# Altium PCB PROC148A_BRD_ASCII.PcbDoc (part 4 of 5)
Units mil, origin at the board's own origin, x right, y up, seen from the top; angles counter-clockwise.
Board outline 7150 x 3764 mil, 4 copper layers (Top Layer, GND01, PWR/GND02, Bottom Layer), stack 60.96 mil thick; 312 components, 352 nets, 2206 pads, 423 vias.
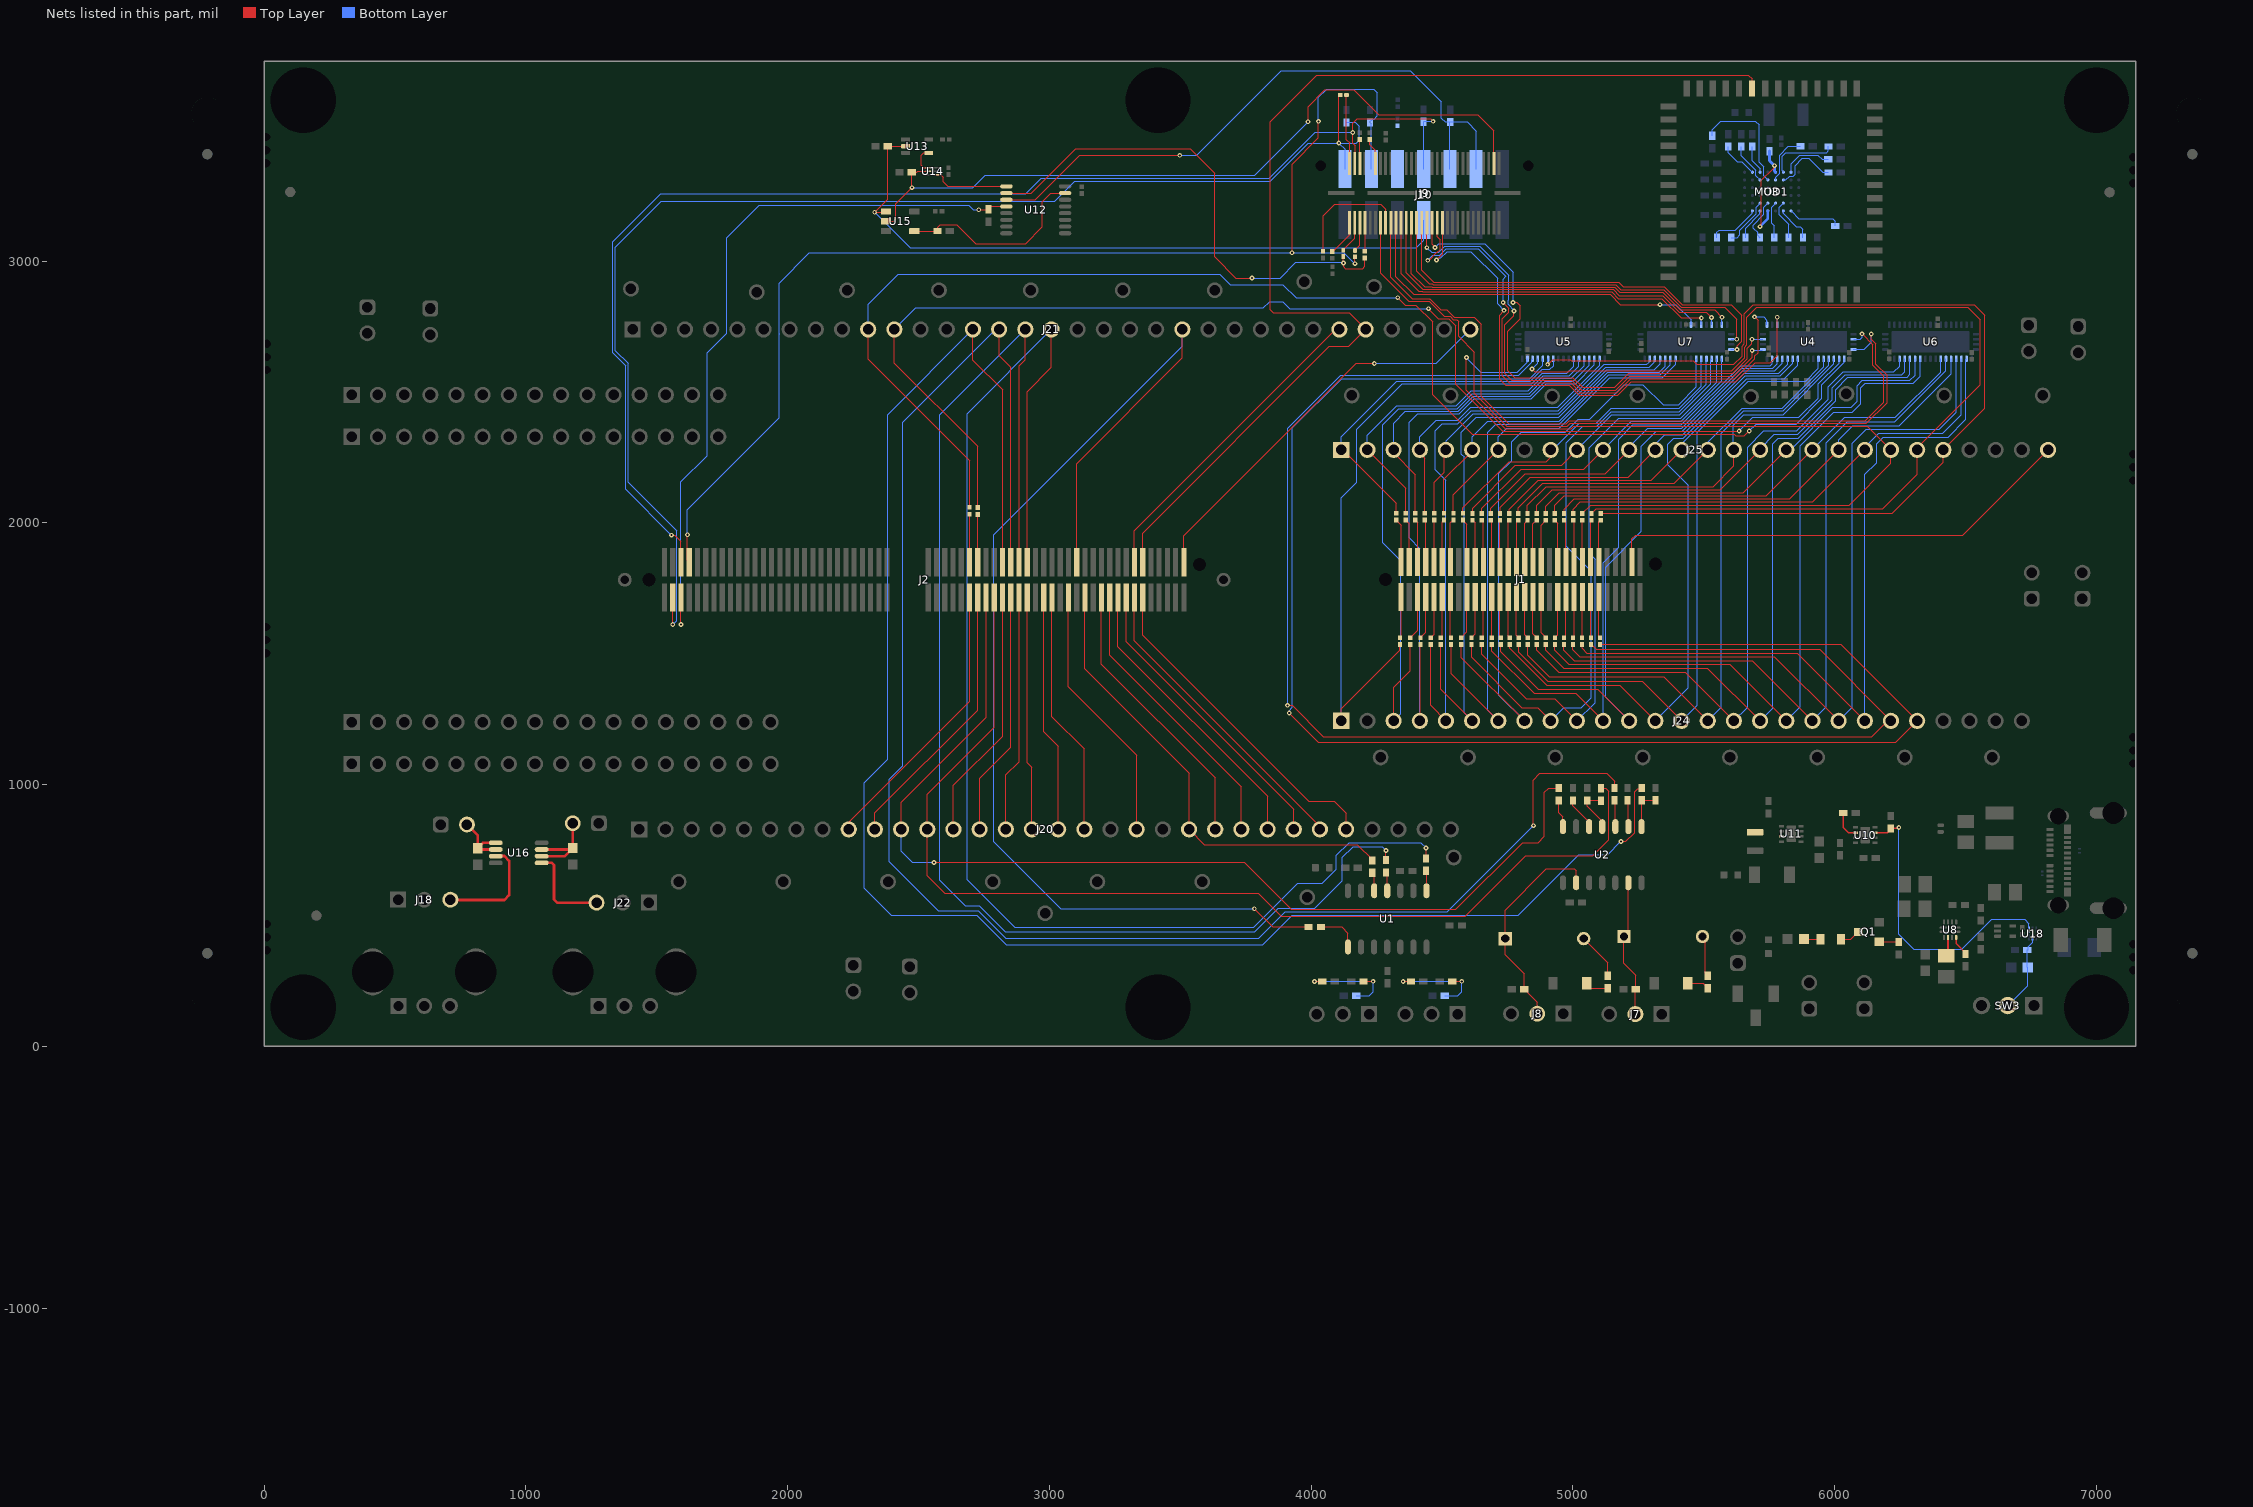
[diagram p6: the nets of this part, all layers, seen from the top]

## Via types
v1: diameter 18, hole 8, Top Layer to Bottom Layer, tented both sides, 422 vias
v2: diameter 18, hole 8, Top Layer to Bottom Layer, 1 vias

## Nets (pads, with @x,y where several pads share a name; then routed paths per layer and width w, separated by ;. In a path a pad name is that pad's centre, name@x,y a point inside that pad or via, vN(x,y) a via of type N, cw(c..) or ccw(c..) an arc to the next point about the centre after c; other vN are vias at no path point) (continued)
HSEC_GPMC0_A0: J25.2 R29.2 U5.6 | length 1303.9
  Top Layer w4: J25.2@4215,2279 4361.43,2132.57 R29.2@4361.43,2037
  Bottom Layer w4: J25.2@4215,2279 4215,2334.41 4327.3,2446.71 4553.99,2446.71 4611.52,2504.24 4829.01,2504.24 4886.53,2561.76 4986.25,2561.76 5023.17,2598.68 U5.6@5023.17,2626.92
HSEC_GPMC0_A1: J24.3 R30.1 U5.5 | length 2376.2
  Top Layer w4: J24.3@4315,1244 4315,1372.51 4378.37,1435.88 R30.1@4378.37,1535
  Bottom Layer w4: J24.3@4315,1244 4342,1271 4342,1855.56 4274.22,1923.34 4274.22,2375.64 4335.29,2436.71 4558.72,2436.71 4616.24,2494.24 4833.15,2494.24 4890.67,2551.76 4993.88,2551.76 5042.86,2600.74 U5.5@5042.86,2626.92
HSEC_GPMC0_A2: J25.3 R31.2 U5.4 | length 1242.1
  Top Layer w4: J25.3@4315,2279 4315,2267.16 4397.86,2184.3 R31.2@4397.86,2037
  Bottom Layer w4: J25.3@4315,2279 4315,2381.36 4360.35,2426.71 4562.36,2426.71 4619.88,2484.24 4837.29,2484.24 4894.81,2541.76 5001.51,2541.76 5062.54,2602.8 U5.4@5062.54,2626.92
HSEC_GPMC0_A3: J24.4 R32.1 U5.3 | length 2271.1
  Top Layer w4: J24.4@4415,1244 4415,1275 4417.4,1277.4 R32.1@4417.4,1535
  Bottom Layer w4: J24.4@4415,1244 4415,1901.65 4374.22,1942.43 4374.22,2383.52 4407.41,2416.71 4565.27,2416.71 4622.79,2474.24 4841.43,2474.24 4898.96,2531.76 5010.73,2531.76 5082.23,2603.25 U5.3@5082.23,2626.92
HSEC_GPMC0_A4: J25.4 R33.2 U5.2 | length 1125
  Top Layer w4: J25.4@4415,2279 4415,2266.4 4434.29,2247.11 R33.2@4434.29,2037
  Bottom Layer w4: J25.4@4415,2279 4415,2329 4477.28,2391.28 4559.36,2391.28 4609.36,2441.28 4941.36,2441.28 5101.91,2601.82 U5.2@5101.91,2626.92
HSEC_GPMC0_A5: J24.5 R34.1 U7.16 | length 2379.2
  Top Layer w4: R34.1@4456.43,1535 4456.43,1302.57 J24.5@4515,1244
  Bottom Layer w4: J24.5@4515,1244 4515,2162.73 4474.22,2203.51 4474.22,2352.01 4500.15,2377.94 4560.17,2377.94 4610.95,2428.73 4943.92,2428.73 5120.43,2605.24 5129.45,2605.24 5281.8,2605.24 5290.7,2614.14 5290.7,2624 U7.16@5293.62,2626.92
HSEC_GPMC0_A6: J25.5 R35.2 U7.15 | length 1228.4
  Top Layer w4: R35.2@4470.71,2037 4470.71,2155.99 4508.3,2193.58 4508.3,2272.3 J25.5@4515,2279
  Bottom Layer w4: J25.5@4515,2279 4516.34,2280.34 4516.34,2313.56 4619.12,2416.35 4945.68,2416.35 5124.57,2595.24 5292.08,2595.24 5310.39,2613.54 5310.39,2624 U7.15@5313.31,2626.92
HSEC_GPMC0_A7: J24.6 R40.1 U7.14 | length 2345.3
  Top Layer w4: R40.1@4495.46,1535 4495.46,1363.54 J24.6@4615,1244
  Bottom Layer w4: J24.6@4615,1244 4584.17,1274.83 4584.17,2252.16 4574.22,2262.11 4574.22,2345.89 4631.35,2403.02 4946.49,2403.02 5128.71,2585.24 5309.71,2585.24 5332.99,2608.51 U7.14@5332.99,2626.92
HSEC_GPMC0_A8: J25.6 R41.2 U7.13 | length 1214.4
  Top Layer w4: R41.2@4507.14,2037 4507.14,2166.01 4615,2273.87 J25.6@4615,2279
  Bottom Layer w4: J25.6@4615,2279 4615,2329 4675.21,2389.21 4946.83,2389.21 5132.86,2575.24 5329.34,2575.24 5352.68,2598.58 U7.13@5352.68,2626.92
HSEC_GPMC0_A9: J24.7 R42.1 U7.12 | length 2312.5
  Top Layer w4: R42.1@4534.48,1535 4534.48,1424.52 J24.7@4715,1244
  Bottom Layer w4: J24.7@4715,1244 4674.22,1284.78 4674.22,2345.89 4704.21,2375.88 4947.64,2375.88 5137,2565.24 5333.48,2565.24 5372.36,2604.12 U7.12@5372.36,2626.92
HSEC_GPMC0_A10: J25.7 R43.2 U7.11 | length 1175.5
  Top Layer w4: R43.2@4543.57,2037 4543.57,2107.57 J25.7@4715,2279
  Bottom Layer w4: J25.7@4715,2279 4715,2329 4747.59,2361.59 4947.5,2361.59 5141.14,2555.23 5340.96,2555.23 5392.05,2606.32 U7.11@5392.05,2626.92
HSEC_GPMC0_A11_TRC_DATA4: J24.10 R98.1 U7.3 | length 2267.9
  Top Layer w4: R98.1@4651.56,1535 4651.56,1498.44 4821.1,1328.9 4930.1,1328.9 J24.10@5015,1244
  Bottom Layer w4: J24.10@5015,1244 5084.4,1313.4 5084.4,1860.72 5061.68,1883.44 5061.68,2287.95 5174.37,2400.64 5412.35,2400.64 5549.53,2537.82 U7.3@5549.53,2626.92
HSEC_GPMC0_A12_TRC_DATA5: J25.11 R99.2 U7.2 | length 1222.6
  Top Layer w4: R99.2@4651.56,2035.98 4651.56,2055.2 4801.88,2205.52 5041.52,2205.52 J25.11@5115,2279
  Bottom Layer w4: J25.11@5115,2279 5223.67,2387.67 5413.52,2387.67 5569.21,2543.36 U7.2@5569.21,2626.92
HSEC_GPMC0_A13_TRC_DATA6: J24.11 R100.1 U4.16 | length 2385.9
  Top Layer w4: R100.1@4689.76,1535.51 4689.76,1510.24 4851.65,1348.35 5010.65,1348.35 J24.11@5115,1244
  Bottom Layer w4: J24.11@5115,1244 5115,1847.83 5174.22,1907.05 5174.22,2319.55 5229,2374.33 5414.32,2374.33 5641.21,2601.22 5753.96,2601.22 5760.92,2608.18 U4.16@5760.92,2626.92
HSEC_GPMC0_A14_TRC_DATA7: J25.12 R101.2 U4.15 | length 1368.5
  Top Layer w4: R101.2@4686.5,2035.98 4686.5,2055.95 4817.37,2186.82 5122.82,2186.82 J25.12@5215,2279
  Bottom Layer w4: J25.12@5215,2279 5215,2291.42 5285.17,2361.59 5415.73,2361.59 5645.36,2591.22 5763.13,2591.22 5780.61,2608.7 U4.15@5780.61,2626.92
HSEC_GPMC0_A15_TRC_DATA8: J24.12 R102.1 U4.14 | length 2457.3
  Top Layer w4: R102.1@4724.26,1535.51 4724.26,1508.13 4868.07,1364.32 5094.68,1364.32 J24.12@5215,1244
  Bottom Layer w4: J24.12@5215,1244 5125,1334 5125,1830.87 5261.7,1967.57 5261.7,2293.47 5318.09,2349.86 5418.14,2349.86 5649.5,2581.22 5771.07,2581.22 5800.29,2610.44 U4.14@5800.29,2626.92
HSEC_GPMC0_A16_TRC_DATA9: J25.13 R103.2 U4.13 | length 1382.5
  Top Layer w4: R103.2@4721.43,2035.98 4721.43,2059.39 4837.1,2175.05 5211.05,2175.05 J25.13@5315,2279
  Bottom Layer w4: J25.13@5315,2279 5315,2300.81 5351.01,2336.82 5419.24,2336.82 5653.64,2571.22 5786,2571.22 5819.98,2605.2 U4.13@5819.98,2626.92
HSEC_GPMC0_A17_TRC_DATA10: J24.13 R104.1 U4.12 | length 2450.1
  Top Layer w4: R104.1@4758.75,1535.51 4758.75,1520.25 4899.54,1379.46 5179.54,1379.46 J24.13@5315,1244
  Bottom Layer w4: J24.13@5315,1244 5440.96,1369.96 5440.96,2143.92 5361.89,2222.99 5361.89,2299.84 5385.13,2323.08 5420.7,2323.08 5658.84,2561.22 5791.31,2561.22 5839.66,2609.57 U4.12@5839.66,2626.92
HSEC_GPMC0_A18_TRC_DATA11: J25.14 R105.2 U4.11 | length 1385.2
  Top Layer w4: R105.2@4756.36,2035.98 4756.36,2051.36 4868.28,2163.28 5299.28,2163.28 J25.14@5415,2279
  Bottom Layer w4: J25.14@5415,2279 5415,2303.08 5663.14,2551.22 5808.15,2551.22 5859.35,2602.42 U4.11@5859.35,2626.92
HSEC_GPMC0_A19_TRC_DATA12: J24.14 R106.1 U4.7 | length 2488.1
  Top Layer w4: R106.1@4793.25,1535.51 4793.25,1505.38 4904.01,1394.61 5264.39,1394.61 J24.14@5415,1244
  Bottom Layer w4: J24.14@5415,1244 5474.22,1303.22 5474.22,2345.89 5669.55,2541.22 5888.68,2541.22 5938.09,2590.63 U4.7@5938.09,2626.92
HSEC_GPMC0_A20_TRC_DATA13: J25.15 R107.2 U4.6 | length 1458.5
  Top Layer w4: R107.2@4791.3,2035.98 4791.3,2057.61 4885.2,2151.51 5387.51,2151.51 J25.15@5515,2279
  Bottom Layer w4: J25.15@5515,2279 5515,2307.25 5646.09,2438.34 5799.94,2438.34 5957.77,2596.17 U4.6@5957.77,2626.92
HSEC_GPMC0_A21_TRC_DATA14: J24.15 R108.1 U4.5 | length 2495.3
  Top Layer w4: R108.1@4827.74,1535.51 4827.74,1494.5 4910.06,1412.18 5346.82,1412.18 J24.15@5515,1244
  Bottom Layer w4: J24.15@5515,1244 5566.4,1295.4 5566.4,2342.16 5652.58,2428.34 5804.09,2428.34 5977.46,2601.71 U4.5@5977.46,2626.92
HSEC_GPMC0_AD0: J24.16 R110.1 U6.15 | length 2719
  Top Layer w4: R110.1@4862.23,1535.51 4862.23,1512.82 4945.14,1429.91 5429.09,1429.91 J24.16@5615,1244
  Bottom Layer w4: J24.16@5615,1244 5667.16,1296.16 5667.16,2288.83 5729.5,2351.17 5855.59,2351.17 5976.13,2471.71 5976.13,2520.89 6032.71,2577.47 6226.07,2577.47 6247.91,2599.31 U6.15@6247.91,2626.92
HSEC_GPMC0_AD1: J25.17 R111.2 U6.14 | length 1728
  Top Layer w4: R111.2@4861.16,2035.98 4861.16,2066.45 4921.35,2126.63 5562.63,2126.63 J25.17@5715,2279
  Bottom Layer w4: J25.17@5715,2279 5715,2283.59 5769.37,2337.96 5857.93,2337.96 5989.75,2469.78 5989.75,2516.5 6039.92,2566.67 6256.67,2566.67 6267.6,2577.6 U6.14@6267.6,2626.92
HSEC_GPMC0_AD2: J24.17 R112.1 U6.13 | length 2748
  Top Layer w4: R112.1@4896.73,1535.51 4896.73,1513.74 4965.05,1445.42 5513.58,1445.42 J24.17@5715,1244
  Bottom Layer w4: J24.17@5715,1244 5763.6,1292.6 5763.6,2301.51 5785.16,2323.08 5860.1,2323.08 6003.12,2466.1 6003.12,2509.41 6050.38,2556.67 6276.27,2556.67 6287.28,2567.68 U6.13@6287.28,2626.92
HSEC_GPMC0_AD3: J25.18 R113.2 U6.12 | length 1743.9
  Top Layer w4: R113.2@4896.1,2035.98 4896.1,2063.85 4947.24,2115 5651,2115 J25.18@5815,2279
  Bottom Layer w4: J25.18@5815,2279 5825.9,2289.9 5840.87,2289.9 5992.34,2441.37 6063.41,2441.37 6086.43,2464.39 6086.43,2524.78 6105.67,2544.02 6286.52,2544.02 6306.77,2564.27 6306.77,2626.72 U6.12@6306.97,2626.92
HSEC_GPMC0_AD4: J24.18 R114.1 U6.11 | length 2761.3
  Top Layer w4: R114.1@4931.22,1535.51 4931.22,1513.74 4984.35,1460.61 5598.39,1460.61 J24.18@5815,1244
  Bottom Layer w4: J24.18@5815,1244 5868.63,1297.63 5868.63,2294.08 5997.02,2422.47 6067.15,2422.47 6099.3,2454.62 6099.3,2516.84 6116.48,2534.02 6300.97,2534.02 6326.65,2559.7 U6.11@6326.65,2626.92
HSEC_GPMC0_AD5: J25.19 R115.2 U6.7 | length 1766.8
  Top Layer w4: R115.2@4931.03,2035.98 4931.03,2066.81 4967.59,2103.37 5739.37,2103.37 J25.19@5915,2279
  Bottom Layer w4: J25.19@5915,2279 6038.79,2402.79 6231.79,2402.79 6405.39,2576.39 U6.7@6405.39,2626.92
HSEC_GPMC0_AD6: J24.19 R116.1 U6.6 | length 2782.7
  Top Layer w4: R116.1@4965.72,1535.51 4965.72,1514.06 5005.97,1473.81 5685.19,1473.81 J24.19@5915,1244
  Bottom Layer w4: J24.19@5915,1244 5967.82,1296.82 5967.82,2305.39 6048.3,2385.87 6229.01,2385.87 6425.08,2581.93 U6.6@6425.08,2626.92
HSEC_GPMC0_AD7: J25.20 R117.2 U6.5 | length 1789.7
  Top Layer w4: R117.2@4965.97,2035.98 4965.97,2053 5004.47,2091.5 5827.5,2091.5 J25.20@6015,2279
  Bottom Layer w4: J25.20@6015,2279 6015,2318.16 6068.47,2371.63 6246.26,2371.63 6444.76,2570.13 U6.5@6444.76,2626.92
HSEC_GPMC0_AD8: J24.20 R118.1 U6.4 | length 2880
  Top Layer w4: R118.1@5000.21,1535.51 5000.21,1514.88 5025.73,1489.36 5769.64,1489.36 J24.20@6015,1244
  Bottom Layer w4: J24.20@6015,1244 6066.47,1295.47 6066.47,2303.31 6121.39,2358.23 6400.21,2358.23 6464.45,2422.47 U6.4@6464.45,2626.92
HSEC_GPMC0_AD9: J25.21 R119.2 U6.3 | length 1868.7
  Top Layer w4: R119.2@5000.9,2035.98 5000.9,2052.48 5028.28,2079.86 5915.86,2079.86 J25.21@6115,2279
  Bottom Layer w4: J25.21@6115,2279 6115,2289.73 6167.43,2342.16 6412.3,2342.16 6484.13,2413.99 U6.3@6484.13,2626.92
HSEC_GPMC0_AD10: J24.21 R120.1 U6.2 | length 2900
  Top Layer w4: R120.1@5034.71,1535.51 5034.71,1520.21 5053,1501.92 5857.08,1501.92 J24.21@6115,1244
  Bottom Layer w4: J24.21@6115,1244 6115,2185.96 6159.72,2230.68 6159.72,2303.03 6184.71,2328.02 6434,2328.02 6501.08,2395.1 6501.08,2624.19 U6.2@6503.82,2626.92
HSEC_GPMC0_AD11: J25.22 R121.2 U5.16 | length 3443.8
  Top Layer w4: v1(4593.12,2631.41) 4593.12,2507.62 4741.48,2359.25 4992.76,2359.25 5003.55,2370.04 6123.96,2370.04 J25.22@6215,2279 6215,2227.25 6055.8,2068.05 5067.9,2068.05 R121.2@5035.83,2035.98
  Bottom Layer w4: v1(4593.12,2631.41) 4648.4,2576.13 4787.9,2576.13 4826.32,2614.55 U5.16@4826.32,2626.92
HSEC_GPMC0_AD12: J24.22 R122.1 U5.15 | length 5756.5
  Top Layer w4: v1(3909.84,1303.13) 3926.91,1303.13 4046.68,1183.36 6142.26,1183.36 6202.9,1244 J24.22@6215,1244 5942.64,1516.36 5088.35,1516.36 R122.1@5069.2,1535.51
  Bottom Layer w4: v1(3909.84,1303.13) 3909.84,2361.58 4112.89,2564.63 4793.16,2564.63 4843.09,2614.55 4843.09,2624 U5.15@4846.01,2626.92
HSEC_GPMC0_AD13: J25.23 R123.2 U5.14 | length 3970.1
  Top Layer w4: v1(4843.69,2588.04) 4854.97,2576.76 4981.71,2576.76 4986.49,2581.54 5605.84,2581.54 5655.87,2631.57 5655.87,2670.78 5664.83,2679.74 5664.83,2786.11 5702.19,2823.47 6103.75,2823.47 6104.98,2824.7 6507.44,2824.7 6556.51,2775.63 6556.51,2528.18 6315,2286.67 J25.23@6315,2279 6315,2186.35 6183.56,2054.91 5088.91,2054.91 5070.77,2036.77 R123.2@5070.77,2035.98
  Bottom Layer w4: v1(4843.69,2588.04) 4865.69,2610.04 U5.14@4865.69,2626.92
HSEC_GPMC0_AD14: J24.23 R124.1 U5.13 | length 5985.2
  Top Layer w4: v1(3916.41,1273.55) 4027.17,1162.79 6233.79,1162.79 J24.23@6315,1244 6023.49,1535.51 R124.1@5103.69,1535.51
  Bottom Layer w4: v1(3916.41,1273.55) 3916.41,1283.01 3928.71,1295.31 3928.71,2363.31 4116.63,2551.23 4834.16,2551.23 4884.71,2601.78 4884.71,2626.25 U5.13@4885.38,2626.92
HSEC_GPMC0_AD15: J25.24 R125.2 U5.12 | length 3924.5
  Top Layer w4: v1(4903.58,2605.63) 4905.19,2605.63 4922.88,2623.32 4990.53,2623.32 4994.26,2619.59 5459.95,2619.59 5473.06,2606.48 5615.15,2606.48 5645.87,2637.2 5645.87,2674.92 5654.83,2683.88 5654.83,2799.29 5688.01,2832.47 6100.02,2832.47 6101.25,2833.7 6532.59,2833.7 6573.5,2792.79 6573.5,2437.5 J25.24@6415,2279 6415,2230.84 6220.14,2035.98 R125.2@5105.7,2035.98
  Bottom Layer w4: v1(4903.58,2605.63) 4904.32,2606.37 4904.32,2626.18 U5.12@4905.06,2626.92
HSEC_GPMC0_BE0N_CLE_TRC_DATA1: J25.9 R45.2 U7.6 | length 1249.5
  Top Layer w4: R45.2@4580,2037 4580,2056.9 4757.02,2233.92 4897.47,2233.92 4922.35,2258.8 4922.35,2271.65 J25.9@4915,2279
  Bottom Layer w4: J25.9@4915,2279 4923.3,2279 5024.91,2380.61 5088.33,2380.61 5146.06,2438.34 5405.66,2438.34 5489.84,2522.52 5489.84,2626.29 U7.6@5490.47,2626.92
HSEC_GPMC0_BEN1_TRC_DATA2: J24.9 R46.1 U7.5 | length 2381.8
  Top Layer w4: R46.1@4612.54,1535 4612.54,1486.06 4804.43,1294.17 4864.83,1294.17 J24.9@4915,1244
  Bottom Layer w4: J24.9@4915,1244 4965.53,1294.54 5031.48,1294.54 5069.09,1332.15 5069.09,1815.86 4974.22,1910.73 4974.22,2305.89 5038.11,2369.78 5091.64,2369.78 5147.29,2425.43 5406.9,2425.43 5510.16,2528.69 U7.5@5510.16,2626.92
HSEC_GPMC0_CLK: J2.110 J21.29 MOD1.51 | length 4358.5
  Top Layer w4: J2.110@3356.37,1849.59 3356.37,1961.37 4069.93,2674.93 4143.88,2674.93 J21.29@4207.95,2739 4144.66,2802.29 3855.37,2802.29 3843.18,2814.48 3843.18,3531.58 4021.81,3710.21 5669.81,3710.21 5684.29,3695.73 MOD1.51@5684.29,3659.36 MOD1.51@5686.03,3657.62
HSEC_GPMC0_CSN0_TRC_DATA15: J25.16 R109.2 U4.4 | length 1540.3
  Top Layer w4: R109.2@4826.23,2035.98 4826.23,2066.63 4897.22,2137.62 5535.1,2137.62 5615,2217.52 J25.16@5615,2279
  Bottom Layer w4: J25.16@5615,2279 5612.01,2281.99 5612.01,2372.77 5652.03,2412.79 5802.68,2412.79 5997.14,2607.26 U4.4@5997.14,2626.92
HSEC_GPMC0_OEN_REN_TRC_DATA0: J24.8 R44.1 U7.7 | length 2481.9
  Top Layer w4: R44.1@4573.51,1535 4573.51,1485.49 J24.8@4815,1244
  Bottom Layer w4: J24.8@4815,1244 4717.08,1341.92 4717.08,2188.75 4765.39,2237.06 4765.39,2309.21 4802.07,2345.89 4970.74,2345.89 5020.95,2396.1 5064.21,2396.1 5195.95,2527.84 5267.54,2527.84 5344.1,2451.28 5403.83,2451.28 5472.04,2519.49 5472.04,2625.67 U7.7@5470.79,2626.92
HSEC_GPMC0_WAIT0: J24.1 R27.1 U5.7 | length 2480.4
  Top Layer w4: J24.1@4115,1244 4115,1290 4115.36,1290 4339.35,1513.99 R27.1@4339.35,1535
  Bottom Layer w4: J24.1@4115,1244 4115,2096.67 4174.22,2155.89 4174.22,2358.22 4347.23,2531.23 4841.86,2531.23 4882.39,2571.76 4977.29,2571.76 5003.49,2597.96 U5.7@5003.49,2626.92
HSEC_GPMC0_WEN_TRC_DATA3: J25.10 R97.2 U7.4 | length 1224.4
  Top Layer w4: R97.2@4616.63,2035.98 4616.63,2056.63 4780.6,2220.6 4956.6,2220.6 J25.10@5015,2279
  Bottom Layer w4: J25.10@5015,2279 5148.79,2412.79 5408.4,2412.79 5526.92,2531.31 5526.92,2624 U7.4@5529.84,2626.92
HSEC_GPMC0_WPN: J25.1 R28.2 U5.11 | length 1332.3
  Top Layer w4: J25.1@4115,2279 4121.23,2279 4325,2075.23 R28.2@4325,2037
  Bottom Layer w4: J25.1@4115,2279 4115,2329 4327.23,2541.23 4837.71,2541.23 4883.24,2586.75 4911.39,2586.75 4925.77,2601.13 4925.77,2625.89 U5.11@4924.75,2626.92
HSEC_I2C1_SCL: J2.87 J20.18 | length 937.9
  Top Layer w4: J2.87@3009.92,1715.73 3009.92,1260.08 3133.54,1136.46 J20.18@3133.54,829
HSEC_I2C1_SDA: J2.85 J20.17 | length 909.6
  Top Layer w4: J2.85@2978.42,1715.73 2978.42,1201.58 3033.54,1146.46 J20.17@3033.54,829
HSEC_LIN1_RXD: J2.76 J21.14 R88.1 | length 6643.5
  Top Layer w4: J21.14@2707.95,2739 2707.95,2621.2 2820.94,2508.21 J2.76@2820.94,1849.59 ; v1(5183.23,782.9) 5202.54,782.9 5235.49,815.85 5235.49,972.75 5247.64,984.9 5262.77,984.9 R88.1@5262.77,987.24
  Bottom Layer w4: J21.14@2707.95,2739 2382.4,2413.46 2382.4,1097.3 2292.76,1007.66 2292.76,604.9 2396.43,501.23 2722.77,501.23 2835.88,388.12 3814.88,388.12 3927.99,501.23 4791.35,501.23 5022.12,732 5132.33,732 v1(5183.23,782.9)
HSEC_LIN1_TXD: J2.78 J21.15 R89.1 | length 6416.7
  Top Layer w4: J21.15@2807.95,2739 2807.95,2638.15 2852.44,2593.66 J2.78@2852.44,1849.59 ; v1(4849.1,843.42) 4848,844.52 4848,1017 4874.17,1043.17 5128.55,1043.17 5159.37,1012.35 R89.1@5159.37,987.24
  Bottom Layer w4: J21.15@2807.95,2739 2794.34,2739 2440.51,2385.17 2440.51,1072.92 2388.76,1021.17 2388.76,706.01 2576.09,518.68 2727.32,518.68 2833.23,412.77 3799.77,412.77 3901,514 4519.68,514 v1(4849.1,843.42)
HSEC_LIN3_RXD: J2.73 J20.12 R91.1 | length 4178.8
  Top Layer w4: J2.73@2789.44,1715.73 2789.44,1220.16 2533.54,964.26 J20.12@2533.54,829 2533.54,652.46 2601,585 3797,585 3885,497 4589,497 4820,728 5076,728 5137.34,789.34 5137.34,974.37 5125.85,985.87 R91.1@5106.88,985.87
HSEC_LIN3_TXD: J2.71 J20.11 R92.1 | length 3998.8
  Top Layer w4: J20.11@2433.54,829 2433.54,932.38 2757.95,1256.79 J2.71@2757.95,1715.73 ; v2(2559,703) 3744.26,703 3923.26,524 4553,524 4807.66,778.66 4867.66,778.66 4891,802 4891,971 4906.78,986.78 R92.1@4945.86,986.78
  Bottom Layer w4: J20.11@2433.54,829 2433.54,746.46 2477,703 v2(2559,703)
HSEC_MCAN0_RX: J2.80 J21.16 R4.1 | length 5154.2
  Top Layer w4: J2.80@2883.93,1849.59 2883.93,2600.09 2907.95,2624.11 J21.16@2907.95,2739 ; R4.1@4285.8,712.09 4285.8,748.55 v1(4286.09,748.84)
  Bottom Layer w4: J21.16@2907.95,2739 2581.69,2412.74 2581.69,634.56 2678.06,538.19 2732.81,538.19 2832.21,438.79 3784.65,438.79 3873.86,528 4014.35,528 4118.99,632.64 4118.99,722.28 4160.06,763.35 4271.58,763.35 v1(4286.09,748.84)
HSEC_MCAN0_TX: J2.82 J21.17 R3.1 | length 5204.2
  Top Layer w4: J2.82@2915.43,1849.59 2915.43,2501.13 3007.95,2593.65 J21.17@3007.95,2739 ; v1(4438.73,758.19) 4438.92,758 R3.1@4438.92,718.35
  Bottom Layer w4: J21.17@3007.95,2739 2686.65,2417.7 2686.65,636.81 2868.46,455 3781,455 3949,623 4043,623 4096.55,676.55 4096.55,730.04 4145.21,778.7 4418.22,778.7 v1(4438.73,758.19)
HSEC_MCAN2_RX: J2.94 J21.22 R7.1 | length 4648.3
  Top Layer w4: J2.94@3104.41,1849.59 3104.41,2226.75 3507.95,2630.29 J21.22@3507.95,2739 ; v1(3783,526) 3852.4,456.6 R7.1@3990.09,456.6
  Bottom Layer w4: J21.22@3507.95,2739 3507.95,2674.92 2788.21,1955.18 2788.21,782.13 3044.34,526 v1(3783,526)
HSEC_MCAN2_TX: J2.95 J20.22 R6.1 | length 1802.2
  Top Layer w4: J2.95@3135.9,1715.73 3135.9,1442.12 3533.54,1044.48 J20.22@3533.54,829 3591.34,771.2 4176.48,771.2 4233.03,714.65 R6.1@4233.03,710.72
HSEC_MII0_RXER: J2.108 J21.28 | length 1221.9
  Top Layer w4: J2.108@3324.88,1849.59 3324.88,1969.88 4094,2739 J21.28@4107.95,2739
HSEC_PORz: J2.120 J21.33 | length 1521.8
  Top Layer w4: J2.120@3513.85,1849.59 3513.85,1950.91 4171.87,2608.92 v1(4241.34,2608.92)
  Bottom Layer w4: v1(4241.34,2608.92) 4477.87,2608.92 J21.33@4607.95,2739
HSEC_SAFETY_ERROR: J1.178 J25.28 | length 1818.7
  Top Layer w4: J1.178@5225.2,1850.93 5225.2,1939.03 5239.57,1953.4 6489.4,1953.4 J25.28@6815,2279
HSEC_SDFM0_CLK1: J2.101 J20.24 | length 1095.1
  Top Layer w4: J2.101@3230.39,1715.73 3230.39,1494.87 3733.54,991.72 J20.24@3733.54,829
HSEC_SDFM0_CLK2: J2.105 J20.26 | length 1151.9
  Top Layer w4: J2.105@3293.38,1715.73 3293.38,1546.62 3933.54,906.46 J20.26@3933.54,829
HSEC_SDFM0_CLK3: J2.109 J20.28 | length 1265.8
  Top Layer w4: J2.109@3356.37,1715.73 3356.37,1571.13 3990.3,937.2 4087.8,937.2 4133.54,891.46 J20.28@4133.54,829
HSEC_SDFM0_D0: J2.91 J20.20 | length 994.7
  Top Layer w4: J2.91@3072.91,1715.73 3072.91,1373.61 3333.54,1112.98 J20.20@3333.54,829
HSEC_SDFM0_D1: J2.99 J20.23 | length 1066.8
  Top Layer w4: J2.99@3198.89,1715.73 3198.89,1460.62 3633.54,1025.98 J20.23@3633.54,829
HSEC_SDFM0_D2: J2.103 J20.25 | length 1123.5
  Top Layer w4: J2.103@3261.89,1715.73 3261.89,1526.73 3833.54,955.07 J20.25@3833.54,829
HSEC_SDFM0_D3: J2.107 J20.27 | length 1180.3
  Top Layer w4: J2.107@3324.88,1715.73 3324.88,1550.12 4033.54,841.46 J20.27@4033.54,829
HSEC_SPI0_D0: J2.67 J20.9 | length 1077.9
  Top Layer w4: J20.9@2233.54,829 2233.54,856.73 2694.96,1318.15 J2.67@2694.96,1715.73
HSEC_SPI0_D1: J2.69 J20.10 | length 1049.5
  Top Layer w4: J20.10@2333.54,829 2333.54,891.85 2726.45,1284.76 J2.69@2726.45,1715.73
HSEC_SPI1_CLK: J2.79 J20.15 | length 907.6
  Top Layer w4: J20.15@2833.54,829 2833.54,1037.6 2883.93,1087.99 J2.79@2883.93,1715.73
HSEC_SPI1_CS0: J2.81 J20.16 | length 894.2
  Top Layer w4: J2.81@2915.43,1715.73 2915.43,1083.81 2933.54,1065.7 J20.16@2933.54,829
HSEC_SPI1_D0: J2.75 J20.13 | length 964.4
  Top Layer w4: J20.13@2633.54,829 2633.54,998.3 2820.94,1185.7 J2.75@2820.94,1715.73
HSEC_SPI1_D1: J2.77 J20.14 | length 936
  Top Layer w4: J20.14@2733.54,829 2733.54,1024.77 2852.44,1143.67 J2.77@2852.44,1715.73
HSEC_TCK: J2.5 R82.2 U12.4 | length 2787.2
  Top Layer w4: v1(1592.59,1611.92) J2.5@1592.59,1715.73 ; v1(2730.11,3196.39) 2766.37,3196.39 R82.2@2767.9,3197.92 2767.9,3198.91 2777.71,3208.72 U12.4@2835.71,3208.72
  Bottom Layer w4: v1(1592.59,1611.92) 1592.59,2156.28 1692.55,2256.24 1692.55,2650.75 1767.17,2725.37 1767.17,3090.17 1890.98,3213.98 2692.26,3213.98 2709.85,3196.39 v1(2730.11,3196.39)
HSEC_TDI: J2.8 J10.3 R21.2 R38.2 | length 4695.2
  Top Layer w4: v1(1617.24,1954.72) 1617.24,1856.44 J2.8@1624.09,1849.59 ; v1(3926.88,3032.03) 3926.88,3370.64 4027.95,3471.71 v1(4027.95,3534.11) ; v1@4167.39,2990.15 R21.2@4167.39,3016.55
  Bottom Layer w4: v1(1617.24,1954.72) 1617.24,2050.6 1968.47,2401.83 1968.47,2720.81 1967.17,2722.11 1967.17,2915.99 2083.61,3032.43 4125.11,3032.43 v1(4167.41,2990.13) ; v1(4027.95,3534.11) 4027.95,3625.57 4058.86,3656.48 4239.85,3656.48 4252.73,3643.6 4252.73,3555.02 4240.2,3542.49 4234.41,3542.49 4224.6,3532.68 R38.2@4224.6,3529.76 4230,3524.36 J10.3@4230,3351.64
HSEC_TDO: J2.6 J9.4 J10.7 R37.2 | length 5033.3
  Top Layer w4: v1(1556.22,1953.13) 1569.5,1953.13 1592.59,1930.04 J2.6@1592.59,1849.59 ; J9.4@4166.52,3372.89 4167.88,3374.25 4167.88,3441.35 4158.73,3450.5 v1(4158.73,3491.5) 4158.73,3526.65 4175.31,3543.23 4456.69,3543.23 v1(4466.15,3533.77)
  Bottom Layer w4: v1(1556.22,1953.13) 1380.78,2128.57 1380.78,2600.89 1331.61,2650.06 1331.61,3073.36 1515.69,3257.44 2910.39,3257.44 2968.68,3315.73 3840.23,3315.73 4016,3491.5 v1(4158.73,3491.5) ; J10.7@4430,3351.64 4430,3531.6 4432.17,3533.77 v1(4466.15,3533.77)
HSEC_TMS: J2.3 J10.1 R18.1 R39.2 | length 5062.4
  Top Layer w4: v1(1561.1,1611.92) J2.3@1561.1,1715.73 ; v1(4105.81,3451.19) 4105.81,3629.61 R18.1@4110.94,3634.74
  Bottom Layer w4: v1(1561.1,1611.92) 1575.85,1626.67 1575.85,1969.63 1390.78,2154.7 1390.78,2609.37 1341.61,2658.54 1341.61,3052.94 1517.96,3229.29 3020.71,3229.29 3097.09,3305.67 3844.31,3305.67 3989.83,3451.19 v1(4105.81,3451.19) ; J10.1@4130,3351.64 4130,3427 v1(4105.81,3451.19) ; R39.2@4134.6,3529.76 4168.69,3529.76 4183.19,3515.26 4183.19,3461.52 4172.86,3451.19 v1(4105.81,3451.19)
HSEC_TRC_CLK: J21.10 R24.2 U4.2 | length 5292.5
  Top Layer w4: J21.10@2307.95,2739 2307.95,2624.2 2694.96,2237.19 R24.2@2694.96,2059.48 ; v1(4330.96,2860.36) 4359.42,2831.9 4400.33,2831.9 4463.93,2768.3 4463.93,2489.21 4615.41,2337.73 4729.46,2337.73 4729.53,2337.67 5616.78,2337.67 5622.15,2332.3 5653.74,2332.3 5672.62,2351.17 v1(5673.38,2351.17)
  Bottom Layer w4: J21.10@2307.95,2739 2307.95,2835.2 2422.52,2949.77 3651.64,2949.77 3691.44,2909.97 3892.13,2909.97 3942.68,2859.42 4330.02,2859.42 v1(4330.96,2860.36) ; v1(5673.38,2351.17) 5699.51,2377.3 5852.37,2377.3 5950.34,2475.27 5950.34,2527.86 6036.51,2614.03 U4.2@6036.51,2626.92
HSEC_TRC_CTL: J21.11 R26.2 U4.3 | length 4958.3
  Top Layer w4: J21.11@2407.95,2739 2407.95,2610.78 2726.45,2292.28 R26.2@2726.45,2058.48 ; v1(4447.87,2818.3) 4486.39,2779.78 4524.84,2779.78 4552.19,2752.43 4552.19,2529.15 4731.76,2349.57 4731.99,2349.57 4732.31,2349.25 5619.4,2349.25 ; 5619.44,2349.29 5632.94,2349.29 v1(5634.82,2351.17)
  Bottom Layer w4: J21.11@2407.95,2739 2489.96,2821.01 3816.53,2821.01 3841.12,2845.6 3891.25,2845.6 3918.55,2818.3 v1(4447.87,2818.3) ; v1(5634.82,2351.17) 5686.44,2402.79 5863.47,2402.79 5937.5,2476.82 5937.5,2531.14 6016.83,2610.47 U4.3@6016.83,2626.92
JTAG_14P_TCK: J10.9 J10.11 R81.2 U12.3 | length 2456.1
  Top Layer w4: U12.3@2835.71,3234.31 2946.48,3234.31 3116.27,3404.1 v1(3498.06,3404.1)
  Bottom Layer w4: v1(3498.06,3404.1) 3562.09,3404.1 3885.25,3727.26 4378.48,3727.26 4497.24,3608.5 4497.24,3545.68 4511.46,3531.46 R81.2@4531,3531.46 ; J10.9@4530,3351.64 4530,3530.46 R81.2@4531,3531.46 ; J10.11@4630,3351.64 4630,3496.8 4595.34,3531.46 R81.2@4531,3531.46
JTAG_MIPI_RTCK: J9.7 R47.2 | length 109.6
  Top Layer w4: R47.2@4204.97,3038.07 4205.89,3039 J9.7@4205.89,3147.3
JTAG_MIPI_TCK: R19.2 R47.1 U12.2 | length 1936.7
  Top Layer w4: U12.2@2835.71,3259.9 2930.98,3259.91 3100.87,3429.8 3538.1,3429.8 3631.62,3336.28 3631.62,3015.95 3712.45,2935.12 v1(3773.69,2935.12) ; R19.2@4122.5,3017.53 4123.2,3016.82 4123.2,2993.41 v1(4123.91,2992.71) 4123.91,2978.11 4130.57,2971.45 4159.4,2971.45 4159.59,2971.26 4196.55,2971.26 4204.97,2979.68 R47.1@4204.97,3012.09
  Bottom Layer w4: v1(3773.69,2935.12) 3881.42,2935.12 3941.31,2995.01 4121.61,2995.01 v1(4123.91,2992.71)
JTAG_MUX_OE: R83.1 U12.15 U15.4 | length 759.8
  Top Layer w4: U15.4@2484.29,3114.75 2572.1,3114.75 R83.1@2572.4,3115.05 2574.02,3116.67 2574.02,3129.65 2583.4,3139.03 2646.6,3139.03 2718.65,3066.98 2909.67,3066.98 2973.65,3130.96 2973.65,3227.52 3006.04,3259.91 U12.15@3060.12,3259.9
JTAG_MUX_SEL: U12.1 U14.4 | length 295
  Top Layer w4: U14.4@2569.29,3329.55 2585.65,3329.55 2594.4,3320.8 2594.4,3303.08 2611.98,3285.5 U12.1@2835.71,3285.5
JTAG_MUX_SEL_14P: J10.8 R79.1 U13.2 U15.1 | length 2627.4
  Top Layer w4: U15.1@2376.02,3189.55 2373.18,3186.71 v1(2332.58,3186.71) 2382.91,3237.04 R79.1@2382.91,3438.96 U13.2@2450.71,3438.96
  Bottom Layer w4: v1(2332.58,3186.71) 2467.68,3051.61 4401.57,3051.61 4430,3080.04 J10.8@4430,3156.76
JTAG_MUX_SEL_14P_INV: U13.4 U14.1 | length 102.3
  Top Layer w4: U14.1@2537.8,3357.11 2519.74,3357.11 2509.7,3367.15 2509.7,3403.56 2519.23,3413.09 2539.01,3413.09 U13.4@2539.29,3413.37
JTAG_MUX_SEL_MIPI: J9.58 R80.1 U14.2 U15.2 | length 2912.8
  Top Layer w4: U15.2@2376.02,3152.15 2406.07,3152.15 2413.56,3159.64 2413.56,3219 2474.29,3279.73 R80.1@2474.29,3339.55 2494.08,3339.55 2497.86,3343.33 U14.2@2537.8,3343.33 ; v1(3988.19,3532.44) 3987.95,3532.68 3987.95,3590.39 4052,3654.44 4162.88,3654.44 4257.67,3559.65 4636.3,3559.65 4698.02,3497.93 J9.58@4698.02,3372.89
  Bottom Layer w4: v1(2475.02,3280.46) 2707.26,3280.46 2755.11,3328.31 3784.06,3328.31 v1(3988.19,3532.44)
JTAG_VTREF: J10.5 R23.1
LIN1_EN: R87.2 U2.2 | length 102
  Top Layer w4: R87.2@5207.87,940 5211.97,935.9 U2.2@5211.97,839.74
LIN1_OUT: C6.1 J7.2 SW1.1 U2.13 | length 527.8
  Top Layer w4: U2.13@5211.97,625.17 5211.97,436.97 SW1.1@5195,420 5195,317.7 5240,272.7 C6.1@5240,218.72 5238.62,217.34 J7.2@5238.62,123.66
LIN1_RXD: R85.1 R88.2 U2.1 | length 153.2
  Top Layer w4: U2.1@5261.97,839.74 5261.97,939.21 R88.2@5262.77,940 R85.1@5315.34,940
LIN1_TXD: R89.2 U2.3 | length 101.3
  Top Layer w4: R89.2@5159.37,940 5161.97,937.4 U2.3@5161.97,839.74
LIN3_EN: R90.2 U2.5 | length 125.5
  Top Layer w4: R90.2@4999.88,939.54 4999.88,918.56 5061.97,856.47 U2.5@5061.97,839.74
LIN3_OUT: C7.1 J8.2 SW2.1 U2.9 | length 833.5
  Top Layer w4: J8.2@4863.69,125 4863.69,168.65 4827.37,204.97 4827.37,208.91 4817.56,218.72 C7.1@4813.62,218.72 4813.62,277.68 4741.02,350.28 SW2.1@4741.02,412.09 4741.02,520.8 4898.22,678 5004.64,678 5011.97,670.67 U2.9@5011.97,625.17
LIN3_RXD: R86.1 R91.2 U2.4 | length 175.8
  Top Layer w4: R91.2@5106.88,938.62 5105.96,939.54 R86.1@5054.88,939.54 5054.88,917.79 5111.97,860.7 U2.4@5111.97,839.74
LIN3_TXD: R92.2 U2.7 | length 106.5
  Top Layer w4: R92.2@4945.86,939.54 4945.86,893.31 4961.97,877.19 U2.7@4961.97,839.74
MCAN0_RX_R: R4.2 U1.4 | length 72.3
  Top Layer w4: R4.2@4285.8,664.85 4290.64,660.01 U1.4@4290.64,594.55
MCAN0_TX_R: R3.2 U1.1 | length 77.3
  Top Layer w4: R3.2@4438.92,671.11 4440.64,669.39 U1.1@4440.64,594.55
MCAN2_RX_R: R7.2 U1.8 | length 165.5
  Top Layer w4: R7.2@4037.33,456.6 4116,456.6 4140.64,431.96 U1.8@4140.64,379.98
MCAN2_TX_R: R6.2 U1.5 | length 72.1
  Top Layer w4: R6.2@4233.03,663.47 4240.64,655.86 U1.5@4240.64,594.55
MIPI_DBG_DETECT: J9.15 R25.2 | length 452.2
  Top Layer w4: R25.2@4045.41,3037.64 4045.41,3172.85 4090.14,3217.58 4265.76,3217.58 4284.63,3198.71 J9.15@4284.63,3147.3
MIPI_TCK: J9.3 R19.1 | length 124
  Top Layer w4: R19.1@4122.5,3041.49 4122.5,3043.29 4166.52,3087.31 J9.3@4166.52,3147.3
MIPI_TDI: J9.5 R21.1 | length 114.6
  Top Layer w4: R21.1@4167.39,3040.51 4167.39,3042.31 4186.21,3061.13 J9.5@4186.21,3147.3
MIPI_TGTRST: J9.6 R17.1 | length 91.7
  Top Layer w4: R17.1@4186.1,3464.52 4186.21,3464.41 J9.6@4186.21,3372.89
MIPI_TMS: J9.2 R18.2 | length 266.8
  Top Layer w4: R18.2@4134.9,3634.74 4134.9,3463.92 4146.84,3451.98 J9.2@4146.84,3372.89
MIPI_VREF_DEBUG: J9.1 R15.1 | length 138.9
  Top Layer w4: R15.1@4081.19,3037.18 4083.86,3037.18 4146.84,3100.16 J9.1@4146.84,3147.3
MIPI_VREF_TRC: J9.12 R16.1 | length 100.4
  Top Layer w4: R16.1@4223.99,3464.52 4223.99,3444.8 4245.26,3423.53 J9.12@4245.26,3372.89
NetC3_1: C3.1 R1.1 R2.2 | length 402.7
  Top Layer w4: v1(4351.47,247.7) 4352.24,248.46 R2.2@4381.28,248.46 ; R1.1@4538.53,248.46 4575.16,248.46 v1(4575.4,248.7)
  Bottom Layer w4: v1(4351.47,247.7) 4351.97,248.2 4574.9,248.2 v1(4575.4,248.7) 4575.4,208.4 4560.67,193.67 C3.1@4510.55,193.67
NetC4_1: C4.1 R5.1 R10.2 | length 402.7
  Top Layer w4: v1(4012.95,247.7) 4013.71,248.46 R10.2@4042.76,248.46 ; R5.1@4200,248.46 4236.64,248.46 v1(4236.87,248.7)
  Bottom Layer w4: v1(4012.95,247.7) 4013.45,248.2 4236.37,248.2 v1(4236.87,248.7) 4236.87,208.4 4222.14,193.67 C4.1@4172.02,193.67
NetD1_1: D1.1 R36.2 | length 85.9
  Top Layer w4: D1.1@5438.94,240.72 5496.88,240.72 5501.25,236.35 5505.19,236.35 5515,226.54 R36.2@5515,222.6
NetD5_1: D5.1 R55.1 | length 62.7
  Top Layer w4: R55.1@5882.99,410.07 5945.56,410.07 D5.1@5945.63,410
NetD5_2: D5.2 Q1.3 | length 78.2
  Top Layer w4: D5.2@6024.37,410 6061.89,410 6089.29,437.4 Q1.3@6091.26,437.4
NetD6_1: D6.1 R84.2 | length 88.8
  Top Layer w4: D6.1@5052.69,240.72 5052.69,238.61 5068.7,222.6 R84.2@5132.72,222.6
NetJ1_121: J1.121 R27.2 | length 157.7
  Top Layer w4: R27.2@4339.35,1560.98 4343.31,1564.94 J1.121@4343.31,1717.07
NetJ1_122: J1.122 R28.1 | length 167.7
  Top Layer w4: R28.1@4325,2011.01 4325,2010.22 4343.31,1991.92 J1.122@4343.31,1850.93
NetJ1_124: J1.124 R29.1 | length 165.6
  Top Layer w4: R29.1@4361.43,2011.01 4361.43,2010.22 4374.8,1996.85 J1.124@4374.8,1850.93
NetJ1_125: J1.125 R30.2 | length 167.7
  Top Layer w4: R30.2@4378.37,1560.98 4378.37,1561.77 4406.3,1589.7 J1.125@4406.3,1717.07
NetJ1_126: J1.126 R31.1 | length 163.6
  Top Layer w4: R31.1@4397.86,2011.01 4406.3,2002.57 J1.126@4406.3,1850.93
NetJ1_127: J1.127 R32.2 | length 164.5
  Top Layer w4: R32.2@4417.4,1560.98 4417.4,1561.77 4437.8,1582.17 J1.127@4437.8,1717.07
NetJ1_128: J1.128 R33.1 | length 161.5
  Top Layer w4: R33.1@4434.29,2011.01 4437.8,2007.5 J1.128@4437.8,1850.93
NetJ1_129: J1.129 R34.2 | length 161.4
  Top Layer w4: R34.2@4456.43,1560.98 4456.43,1561.77 4469.29,1574.63 J1.129@4469.29,1717.07
NetJ1_130: J1.130 R35.1 | length 160.7
  Top Layer w4: J1.130@4469.29,1850.93 4469.29,2009.59 R35.1@4470.71,2011.01
NetJ1_131: J1.131 R40.2 | length 158.3
  Top Layer w4: R40.2@4495.46,1560.98 4500.79,1566.32 J1.131@4500.79,1717.07
NetJ1_132: J1.132 R41.1 | length 162.7
  Top Layer w4: J1.132@4500.79,1850.93 4500.87,1851.02 4500.87,2004.74 R41.1@4507.14,2011.01
NetJ1_133: J1.133 R42.2 | length 157
  Top Layer w4: J1.133@4532.28,1717.07 4532.28,1563.18 R42.2@4534.48,1560.98
NetJ1_134: J1.134 R43.1 | length 164.8
  Top Layer w4: J1.134@4532.28,1850.93 4532.28,1999.72 R43.1@4543.57,2011.01
NetJ1_137: J1.137 R44.2 | length 165.1
  Top Layer w4: R44.2@4573.51,1560.98 4573.51,1561.77 4595.28,1583.54 J1.137@4595.28,1717.07
NetJ1_138: J1.138 R45.1 | length 166.4
  Top Layer w4: R45.1@4580,2011.01 4580,2010.22 4595.28,1994.95 J1.138@4595.28,1850.93
NetJ1_139: J1.139 R46.2 | length 162
  Top Layer w4: R46.2@4612.54,1560.98 4612.54,1561.77 4626.77,1576.01 J1.139@4626.77,1717.07
NetJ1_140: J1.140 R97.1 | length 163.3
  Top Layer w4: R97.1@4616.63,2010 4626.77,1999.86 J1.140@4626.77,1850.93
NetJ1_141: J1.141 R98.2 | length 152.6
  Top Layer w4: R98.2@4658.27,1564.49 J1.141@4658.27,1717.07
NetJ1_142: J1.142 R99.1 | length 161.8
  Top Layer w4: R99.1@4651.56,2010 4657.83,2003.73 4657.83,1851.37 J1.142@4658.27,1850.93
NetJ1_143: J1.143 R100.2 | length 155.6
  Top Layer w4: R100.2@4689.76,1561.5 J1.143@4689.76,1717.07
NetJ1_144: J1.144 R101.1 | length 160.4
  Top Layer w4: R101.1@4686.5,2010 4689.76,2006.73 J1.144@4689.76,1850.93
NetJ1_145: J1.145 R102.2 | length 156.8
  Top Layer w4: J1.145@4721.26,1717.07 4721.26,1564.49 R102.2@4724.26,1561.5
NetJ1_146: J1.146 R103.1 | length 159.1
  Top Layer w4: J1.146@4721.26,1850.93 4721.26,2009.83 R103.1@4721.43,2010
NetJ1_147: J1.147 R104.2 | length 158.1
  Top Layer w4: J1.147@4752.76,1717.07 4752.76,1567.49 R104.2@4758.75,1561.5
NetJ1_148: J1.148 R105.1 | length 160.6
  Top Layer w4: J1.148@4752.76,1850.93 4752.76,2006.39 R105.1@4756.36,2010
NetJ1_149: J1.149 R106.2 | length 159.3
  Top Layer w4: J1.149@4784.25,1717.07 4784.25,1570.49 R106.2@4793.25,1561.5
NetJ1_150: J1.150 R107.1 | length 162
  Top Layer w4: J1.150@4784.25,1850.93 4785.03,1851.71 4785.03,2003.73 R107.1@4791.3,2010
NetJ1_151: J1.151 R108.2 | length 160.5
  Top Layer w4: J1.151@4815.75,1717.07 4815.75,1573.49 R108.2@4827.74,1561.5
NetJ1_152: J1.152 R109.1 | length 163.4
  Top Layer w4: J1.152@4815.75,1850.93 4815.75,1999.52 R109.1@4826.23,2010
NetJ1_153: J1.153 R110.2 | length 161.8
  Top Layer w4: J1.153@4847.24,1717.07 4847.24,1577.27 4862.23,1562.28 R110.2@4862.23,1561.5
NetJ1_154: J1.154 R111.1 | length 164.8
  Top Layer w4: J1.154@4847.24,1850.93 4847.24,1996.08 R111.1@4861.16,2010
NetJ1_155: J1.155 R112.2 | length 163
  Top Layer w4: J1.155@4878.74,1717.07 4878.74,1580.27 4896.73,1562.28 R112.2@4896.73,1561.5
NetJ1_156: J1.156 R113.1 | length 166.3
  Top Layer w4: J1.156@4878.74,1850.93 4878.74,1991.85 4896.1,2009.21 R113.1@4896.1,2010
NetJ1_159: J1.159 R114.2 | length 159.9
  Top Layer w4: R114.2@4931.22,1561.5 4941.73,1572.01 J1.159@4941.73,1717.07
NetJ1_160: J1.160 R115.1 | length 163.5
  Top Layer w4: R115.1@4931.03,2010 4941.73,1999.3 J1.160@4941.73,1850.93
NetJ1_161: J1.161 R116.2 | length 158.7
  Top Layer w4: R116.2@4965.72,1561.5 4973.23,1569.01 J1.161@4973.23,1717.07
NetJ1_162: J1.162 R117.1 | length 162.1
  Top Layer w4: R117.1@4965.97,2010 4972.23,2003.73 4972.23,1851.92 J1.162@4973.23,1850.93
NetJ1_163: J1.163 R118.2 | length 157.4
  Top Layer w4: R118.2@5000.21,1561.5 5004.72,1566.01 J1.163@5004.72,1717.07
NetJ1_164: J1.164 R119.1 | length 160.7
  Top Layer w4: R119.1@5000.9,2010 5004.72,2006.17 J1.164@5004.72,1850.93
NetJ1_165: J1.165 R120.2 | length 156.2
  Top Layer w4: R120.2@5034.71,1561.5 5036.22,1563.01 J1.165@5036.22,1717.07
NetJ1_166: J1.166 R121.1 | length 159.2
  Top Layer w4: R121.1@5035.83,2010 5036.22,2009.61 J1.166@5036.22,1850.93
NetJ1_167: J1.167 R122.2 | length 156.2
  Top Layer w4: J1.167@5067.72,1717.07 5067.72,1562.98 R122.2@5069.2,1561.5
NetJ1_168: J1.168 R123.1 | length 160.3
  Top Layer w4: J1.168@5067.72,1850.93 5067.72,2006.95 R123.1@5070.77,2010
NetJ1_169: J1.169 R124.2 | length 157.4
  Top Layer w4: J1.169@5099.21,1717.07 5099.21,1565.98 R124.2@5103.69,1561.5
NetJ1_170: J1.170 R125.1 | length 161.8
  Top Layer w4: J1.170@5099.21,1850.93 5099.43,1851.15 5099.43,2003.73 R125.1@5105.7,2010
NetJ2_68: J2.68 R24.1 | length 183.9
  Top Layer w4: J2.68@2694.96,1849.59 R24.1@2694.96,2033.5
NetJ2_70: J2.70 R26.1 | length 182.9
  Top Layer w4: J2.70@2726.45,1849.59 R26.1@2726.45,2032.5
NetL1_1: L1.1 U11.7
NetQ1_1: Q1.1 R56.1 | length 75.6
  Top Layer w4: Q1.1@6170,400 6243.62,400 R56.1@6245,398.62
NetR11_1: R11.1 U3.D6 U3.E1 | length 418.2
  Top Layer w4: v1(5714.32,3131.83) 5717,3134.51 5717,3140.37 5720.32,3143.69 5720.32,3308.25 5767.17,3355.1 5767.17,3362.14 v1(5769.85,3364.82)
  Bottom Layer w10: v1(5714.32,3131.83) 5744.53,3162.04 U3.D6@5744.53,3191.89
  Bottom Layer w12: R11.1@5750.74,3419.46 5750.74,3383.93 v1(5769.85,3364.82) 5769.85,3343.73 U3.E1@5774.06,3339.53
NetR36_1: R36.1 SW1.2 | length 158.4
  Top Layer w4: SW1.2@5495,420 5495,407.23 5505.19,397.04 5505.19,279.65 R36.1@5515,269.84
NetR51_2: R51.2 U8.4 | length 73.1
  Top Layer w6: R51.2@6425.4,346.34 6432.72,353.65 U8.4@6432.72,416.41
NetR54_2: R54.2 U8.6 | length 77.9
  Top Layer w6: U8.6@6464.21,416.41 6464.21,393.04 6500,357.25 R54.2@6500,353.31
NetR84_1: R84.1 SW2.2 | length 180.2
  Top Layer w4: SW2.2@5041.02,412.09 5132.72,320.4 R84.1@5132.72,269.84
OPAMP1_IN: J18.3 U16.3 | length 422.4
  Top Layer w10: J18.3@711.85,560.53 713.03,559.35 918.03,559.35 936.47,577.8 936.47,709.32 918.53,727.27 U16.3@885.82,727.27
OPAMP1_OUT: C30.1 J65.2 U16.1 U16.2 | length 255.4
  Top Layer w10: J65.2@775.16,847.74 816.38,806.51 C30.1@816.38,758.19 ; U16.2@885.16,752.3 821.28,752.3 C30.1@816.38,757.2 C30.1@816.38,758.19 ; U16.1@885.16,777.89 836.09,777.89 C30.1@816.38,758.19
OPAMP2_IN: J22.3 U16.5 | length 349.5
  Top Layer w10: U16.5@1060.36,701.12 1099.17,701.12 1107.59,692.69 1107.59,561.3 1119.6,549.3 J22.3@1270,549.3
OPAMP2_OUT: C41.1 J66.2 U16.6 U16.7 | length 348.6
  Top Layer w10: U16.6@1060.36,726.71 1149.05,726.71 1179.55,757.21 C41.1@1179.55,758.19 ; U16.7@1060.36,752.3 1173.66,752.3 C41.1@1179.55,758.19 ; J66.2@1179.46,852.31 1179.46,758.28 C41.1@1179.55,758.19
PSRAM_D0: R12.1 U3.B6 | length 194.3
  Bottom Layer w4: R12.1@5550.01,3089.9 5550.01,3110.47 5558.21,3118.67 5620.08,3118.67 5685,3183.6 5685,3191.42 U3.B6@5685.47,3191.89
PSRAM_D1: R48.1 U3.C5 | length 190.2
  Bottom Layer w4: R48.1@5604.8,3089.9 5627.1,3089.9 5637.6,3100.4 5637.6,3117.66 5700.24,3180.3 5700.24,3206.65 U3.C5@5715,3221.42
PSRAM_D2: R59.1 U3.C6 | length 124.9
  Bottom Layer w4: R59.1@5659.59,3089.9 5659.59,3125.51 5714.11,3180.03 5714.11,3191 U3.C6@5715,3191.89
PSRAM_D3: R60.1 U3.D5 | length 165.5
  Bottom Layer w4: R60.1@5714.38,3089.9 5705.25,3099.03 5705.25,3109.56 5688.46,3126.35 5688.46,3136.87 5729.76,3178.17 5729.76,3206.65 U3.D5@5744.53,3221.42
PSRAM_D4: R61.1 U3.E5 | length 141.7
  Bottom Layer w4: R61.1@5769.17,3089.9 5769.17,3134.43 5759.29,3144.3 5759.29,3206.65 U3.E5@5774.06,3221.42
PSRAM_D5: R62.1 U3.F5 | length 153.4
  Bottom Layer w4: U3.F5@5803.58,3221.42 5787.4,3205.23 5787.4,3176.85 5823.95,3140.3 R62.1@5823.95,3089.9
PSRAM_D6: R63.1 U3.F6 | length 141.3
  Bottom Layer w4: U3.F6@5803.58,3191.89 5803.58,3182.29 5854.04,3131.83 5868.03,3131.83 5878.74,3121.11 R63.1@5878.74,3089.9
PSRAM_D7: R64.1 U3.G6 | length 203.2
  Bottom Layer w4: U3.G6@5833.11,3191.89 5862.96,3162.04 5992.16,3162.04 6001.66,3152.54 R64.1@6001.66,3134.19
PSRAM_D8: R65.1 U3.B1 | length 146.4
  Bottom Layer w4: R65.1@5593.58,3437.63 5593.58,3413.94 5606.83,3400.69 5628.01,3379.51 5645.49,3379.51 U3.B1@5685.47,3339.53
PSRAM_D9: R66.1 U3.C1 | length 110.6
  Bottom Layer w4: R66.1@5685.09,3437.75 5685.09,3383.35 5703.44,3365 5715,3353.44 U3.C1@5715,3339.53
PSRAM_D10: R67.1 U3.C2 | length 157.3
  Bottom Layer w4: R67.1@5643.28,3437.63 5643.28,3403.35 5699.18,3347.45 5699.18,3325.82 U3.C2@5715,3310
PSRAM_D11: R68.1 U3.D2 | length 446
  Bottom Layer w4: R68.1@5531.88,3478.45 5531.88,3502.25 5563.99,3534.36 5696.54,3534.36 5710.91,3519.99 5710.91,3378.31 5728.4,3360.82 5728.4,3326.13 U3.D2@5744.53,3310
PSRAM_D12: R69.1 U3.E2 | length 194.5
  Bottom Layer w4: U3.E2@5774.06,3310 5774.06,3320.32 5789.84,3336.11 5789.84,3405.21 5823.28,3438.65 R69.1@5868.69,3438.65
PSRAM_D13: R70.1 U3.F2 | length 248
  Bottom Layer w4: U3.F2@5803.58,3310 5812.76,3310 5827.86,3325.1 5840.8,3325.1 5848.4,3332.7 5848.4,3365 5876.05,3392.65 5900.14,3392.65 5953.74,3339.05 R70.1@5976.2,3339.05
PSRAM_D14: R71.1 U3.F1 | length 264.7
  Bottom Layer w4: U3.F1@5803.58,3339.53 5803.58,3341.61 5799.44,3345.76 5799.44,3399.7 5813.59,3413.84 5968.89,3413.84 5976.22,3421.17 R71.1@5976.22,3438.29
PSRAM_D15: R72.1 U3.G1 | length 194.9
  Bottom Layer w4: U3.G1@5833.11,3339.53 5833.11,3371.51 5866.38,3404.78 5936.05,3404.78 5951.94,3388.88 R72.1@5975.64,3388.88
SW_EN: C44.1 R94.2 SW3.2 U18.2 | length 302.2
  Bottom Layer w4: SW3.2@6661,156 6737,232 C44.1@6737,302 6735.92,303.08 R94.2@6735.92,369 6739.85,369 6739.85,381.7 6755.96,397.81 U18.2@6755.96,415.65
TPS2296_CT: C31.1 U10.6 | length 110.2
  Top Layer w6: C31.1@6032.76,891.89 6032.76,836.24 6051.92,817.08 U10.6@6079.41,817.08
TPS2296_EN: R93.2 U10.3 U18.4 | length 1107
  Top Layer w6: U10.3@6154.22,817.08 6202.2,817.08 6214.01,828.9 R93.2@6214.01,832.83 6241.26,832.83 v1(6245.07,836.64)
  Bottom Layer w4: v1(6245.07,836.64) 6245.07,427.64 6301.07,371.64 6484.75,371.64 6599.1,485.99 6725.41,485.99 6742.18,469.22 U18.4@6742.18,447.15
TRC_CLK_MUX: J9.13 U4.42 | length 2932.6
  Top Layer w4: J9.13@4264.95,3147.3 4264.95,2953.38 4372.38,2845.95 4451.48,2845.95 4507.65,2789.78 4530.4,2789.78 4543.47,2776.71 4556.12,2776.71 4562.98,2769.85 4562.98,2712.74 4623.04,2652.68 4623.04,2494.3 4748.09,2369.25 4979.05,2369.25 4989.84,2380.04 6121.22,2380.04 6200.19,2459.02 6200.19,2563.68 6157.08,2606.79 6157.08,2683.99 6139.48,2701.59 v1(6139.48,2721.44)
  Bottom Layer w4: U4.42@6071.97,2662.38 6111.92,2662.38 6139.48,2689.94 v1(6139.48,2721.44)
TRC_CTL_MUX: J9.17 U4.40 | length 2864.1
  Top Layer w4: J9.17@4304.32,3147.3 4304.32,2937.51 4385.88,2855.95 4452.51,2855.95 4453.51,2854.95 4455.21,2854.95 4495,2815.16 4517.74,2815.16 4547.19,2785.71 4623.61,2785.71 4650.24,2759.08 4650.24,2484.41 4755.4,2379.25 4974.9,2379.25 4985.69,2390.04 6117.08,2390.04 6188.16,2461.13 6188.16,2559.9 6145.91,2602.15 6145.91,2681.02 v1(6104.66,2722.27)
  Bottom Layer w4: U4.40@6071.95,2701.72 6096.86,2701.73 6104.66,2709.53 v1(6104.66,2722.27)
TRC_DATA0_MUX: J9.19 U7.31 | length 1421
  Top Layer w4: J9.19@4324,3147.3 4324,2940.02 4391.34,2872.68 5141.83,2872.68 5180.81,2833.7 v1(5332.5,2833.7)
  Bottom Layer w4: v1(5332.5,2833.7) 5392.65,2833.7 5451.1,2775.25 U7.31@5451.1,2756.84
TRC_DATA1_MUX: J9.21 U7.33 | length 1438.2
  Top Layer w4: J9.21@4343.69,3147.3 4343.69,2951.78 4411.22,2884.25 4424.9,2884.25 4426.45,2882.71 5148.52,2882.71 5174.04,2857.19 5339.68,2857.19 5414.17,2782.7 v1(5490.5,2782.7)
  Bottom Layer w4: U7.33@5490.49,2756.86 v1(5490.5,2782.7)
TRC_DATA2_MUX: J9.23 U7.35 | length 1456
  Top Layer w4: J9.23@4363.37,3147.3 4363.37,2956.51 4426.57,2893.31 4428.57,2893.31 4430.17,2891.71 5153.67,2891.71 5177.45,2867.92 5343.58,2867.92 5406.89,2804.61 5509.39,2804.61 v1(5529.1,2784.9)
  Bottom Layer w4: v1(5529.1,2784.9) 5529.47,2784.53 5529.47,2757.21 U7.35@5529.84,2756.84
TRC_DATA3_MUX: J9.25 U7.37 | length 1479.5
  Top Layer w4: J9.25@4383.06,3147.3 4383.06,2951.55 4433.19,2901.41 4461.34,2901.41 4462.05,2900.71 5158.81,2900.71 5178.83,2880.69 5343.54,2880.69 5410.61,2813.61 5541.31,2813.61 v1(5569.21,2785.71)
  Bottom Layer w4: U7.37@5569.21,2756.84 v1(5569.21,2785.71)
TRC_DATA4_MUX: J9.27 U7.40 | length 1583.2
  Top Layer w4: J9.27@4402.74,3147.3 4402.74,2961.44 4451.36,2912.82 4462.66,2912.82 4465.78,2909.71 5163.95,2909.71 5182.79,2890.87 5346.09,2890.87 5413.49,2823.47 5580.73,2823.47 5625.96,2778.24 v1(5625.96,2701.45)
  Bottom Layer w4: U7.40@5604.65,2701.72 5604.92,2701.45 v1(5625.96,2701.45)
TRC_DATA5_MUX: J9.29 U7.42 | length 1635.8
  Top Layer w4: J9.29@4422.43,3147.3 4422.43,2965.78 4469.1,2919.11 4496.85,2919.11 4497.26,2918.71 5174.88,2918.71 5192.18,2901.41 5349.34,2901.41 5418.29,2832.47 5605.73,2832.47 5644.83,2793.37 5644.83,2693.63 5627,2675.8 v1(5627,2662.77)
  Bottom Layer w4: U7.42@5604.65,2662.35 5604.85,2662.56 5626.79,2662.56 v1(5627,2662.77)
TRC_DATA6_MUX: J9.31 U4.18 | length 1960.5
  Top Layer w4: v1(4442.11,3051.59) J9.31@4442.11,3147.3 ; v1(4774.63,2809.26) 4774.63,2791.07 4740.34,2756.78 4740.34,2571.7 4766.94,2545.1 4995.16,2545.1 5032.77,2507.49 5163.17,2507.49 5216.49,2560.81 5612.65,2560.81 5684.75,2632.91 v1(5684.75,2658.82)
  Bottom Layer w4: v1(4442.11,3051.59) 4460.67,3033.03 4487.62,3033.03 4511.03,3056.43 4644.05,3056.43 4753.9,2946.58 4753.9,2851.55 4752.27,2849.92 4752.27,2834.28 4774.63,2811.92 v1(4774.63,2809.26) ; v1(5684.75,2658.82) 5721.96,2658.82 U4.18@5725.49,2662.35
TRC_DATA7_MUX: J9.33 U4.20 | length 1975.5
  Top Layer w4: J9.33@4461.8,3147.3 4461.8,3063.5 v1(4473.4,3051.9) ; v1(4771.14,2842.1) 4785.39,2842.1 4798.08,2829.41 4798.08,2779.62 4750.34,2731.88 4750.34,2581.68 4776.92,2555.1 4999.31,2555.1 5036.92,2517.49 5159.03,2517.49 5212.35,2570.81 5609.63,2570.81 5665.87,2627.05 5665.87,2666.64 5683.71,2684.47 v1(5683.71,2701.5)
  Bottom Layer w4: v1(4473.4,3051.9) 4487.93,3066.43 4662.4,3066.43 4771.14,2957.69 v1(4771.14,2842.1) ; v1(5683.71,2701.5) 5683.82,2701.61 5725.38,2701.61 U4.20@5725.49,2701.72
TRC_DATA8_MUX: J9.35 U4.22 | length 2220.2
  Top Layer w4: v1(4445.37,3003.03) 4450.64,3003.03 4480.63,3033.03 4481.22,3033.03 4492.27,3044.08 4492.27,3082.33 4481.49,3093.11 J9.35@4481.49,3147.3 ; v1(4733.39,2841.72) 4755.31,2819.8 4755.31,2804.16 4730.24,2779.09 4730.24,2561.8 4756.94,2535.1 4991.02,2535.1 5028.63,2497.49 5167.31,2497.49 5220.63,2550.81 5618.22,2550.81 5694.53,2627.12 5694.53,2638.04 5707.09,2650.59 5707.09,2773.92 v1(5693.99,2787.02)
  Bottom Layer w4: v1(4445.37,3003.03) 4465.37,3023.03 4491.76,3023.03 4515.17,3046.43 4639.09,3046.43 4743.9,2941.62 4733.39,2931.11 v1(4733.39,2841.72) ; v1(5693.99,2787.02) 5728.4,2787.02 5741.24,2774.18 U4.22@5741.24,2756.84
TRC_DATA9_MUX: J9.37 U4.24 | length 2169.4
  Top Layer w4: v1(4478.44,3004.14) 4502.27,3027.97 4502.27,3146.2 J9.37@4501.17,3147.3 ; v1(4736.44,2811.98) 4736.44,2809.57 4720.24,2793.37 4720.24,2548.15 4743.29,2525.1 4986.88,2525.1 5024.49,2487.49 5171.45,2487.49 5222.71,2538.74 5622.06,2538.74 5695.8,2612.47 5754.46,2612.47 5780.61,2638.62 v1(5780.61,2785.71)
  Bottom Layer w4: v1(4478.44,3004.14) 4481.88,3004.14 4490.77,3013.03 4495.9,3013.03 4519.31,3036.43 4609.21,3036.43 4711.85,2933.8 4711.85,2836.57 v1(4736.44,2811.98) ; U4.24@5780.61,2756.84 v1(5780.61,2785.71)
